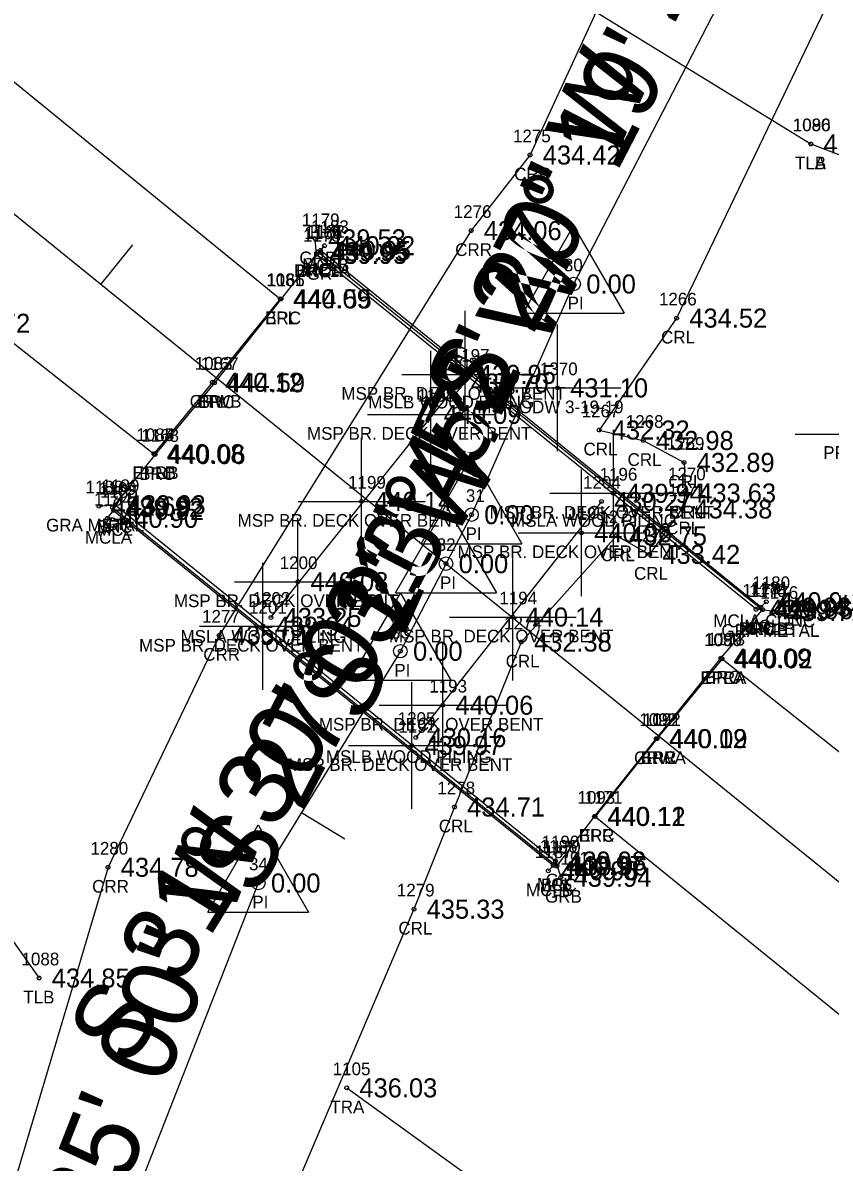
# Model space of a CAD drawing. Extents: x 1611865 to 1617004, y 775289 to 778546.
# Drawn here: x 1614429 to 1614492.7, y 777648.2 to 777738.1 of the extents above; entities that cross this region are included whole.
import ezdxf

# ---------------------------------------------------------------- set-up
doc = ezdxf.new("R2010")
doc.units = 0
for name, color, linetype in [('Default', 7, 'Continuous'), ('RD_EX_Bridge', 7, 'Continuous'), ('RD_EX_Bridge_txCode', 7, 'Continuous'), ('RD_EX_Conc', 7, 'Continuous'), ('RD_EX_Conc_txCode', 7, 'Continuous'), ('RD_EX_GuardRail', 7, 'Continuous'), ('RD_EX_GuardRail_txCode', 7, 'Continuous'), ('RD_EX_H2O', 7, 'Continuous'), ('RD_EX_H2O_txCode', 7, 'Continuous'), ('RD_EX_Misc', 7, 'Continuous'), ('RD_EX_Misc_txCode', 7, 'Continuous'), ('RD_EX_Road', 7, 'Continuous'), ('RD_EX_Road_txCode', 7, 'Continuous'), ('RD_EX_TX_Bridge_ELEV', 7, 'Continuous'), ('RD_EX_TX_Conc_ELEV', 7, 'Continuous'), ('RD_EX_TX_GuardRail_ELEV', 7, 'Continuous'), ('RD_EX_TX_H2O_ELEV', 7, 'Continuous'), ('RD_EX_TX_Misc_ELEV', 7, 'Continuous'), ('RD_EX_TX_Road_ELEV', 7, 'Continuous'), ('RD_EX_TX_VEG_ELEV', 7, 'Continuous'), ('RD_EX_UT', 7, 'Continuous'), ('RD_EX_UT_txCode', 7, 'Continuous'), ('RD_EX_VEG', 7, 'Continuous'), ('RD_EX_VEG_txCode', 7, 'Continuous'), ('RD_HC_Cl', 7, 'Continuous'), ('RD_HC_Data', 7, 'Continuous'), ('RD_HC_Data_Tic', 7, 'Continuous'), ('RD_HC_Survey_ELEV', 7, 'Continuous'), ('RD_HC_Survey_txCode', 7, 'Continuous'), ('RD_HC_txCode', 7, 'Continuous'), ('RD_SMD_Locator', 7, 'Continuous')]:
    doc.layers.add(name, color=color, linetype=linetype)

msp = doc.modelspace()

# ---------------------------------------------------------------- linework, layer by layer
at = {"layer": 'Default'}
for p, q in [((1614235.771, 777878.843), (1615250.563, 777057.494)), ((1614487.003, 777745.62), (1614472.452, 777717.464)), ((1614472.452, 777717.464), (1614464.407, 777699.284)), ((1614464.407, 777699.284), (1614458.798, 777688.523)), ((1614458.798, 777688.523), (1614447.603, 777670.255)), ((1614447.603, 777670.255), (1614430.278, 777626.087))]:
    msp.add_line(p, q, dxfattribs=at)
at = {"layer": 'RD_EX_Bridge'}
msp.add_line((1614452.321, 777720.005), (1614487.341, 777691.793), dxfattribs=at)
msp.add_lwpolyline([(1614452.321, 777720.005), (1614449.4, 777716.289), (1614444.153, 777709.679), (1614439.465, 777704.026), (1614436.12, 777699.854), (1614471.128, 777671.593), (1614474.101, 777675.503), (1614478.969, 777681.635), (1614484.046, 777687.977), (1614487.341, 777691.793)], dxfattribs=at)
at = {"layer": 'RD_EX_Conc'}
for points in [[(1614487.633, 777692.421), (1614487.198, 777691.999), (1614452.506, 777720.113), (1614452.825, 777720.485)], [(1614435.717, 777698.998), (1614436.195, 777699.618), (1614470.857, 777671.642), (1614470.453, 777671.217)]]:
    msp.add_lwpolyline(points, dxfattribs=at)
at = {"layer": 'RD_EX_GuardRail'}
for points in [[(1614488.257, 777691.653), (1614486.822, 777691.831), (1614452.199, 777719.801), (1614452.096, 777721.023)], [(1614435.05, 777699.96), (1614436.32, 777700.065), (1614471.025, 777671.987), (1614471.447, 777670.706)]]:
    msp.add_lwpolyline(points, dxfattribs=at)
at = {"layer": 'RD_EX_H2O'}
for p, q in [((1614471.182, 777704.278), (1614471.182, 777714.278)), ((1614466.182, 777709.278), (1614476.182, 777709.278))]:
    msp.add_line(p, q, dxfattribs=at)
for points in [[(1614634.128, 778230.422), (1614629.458, 778175.603), (1614612.201, 778126.551), (1614606.674, 778108.168), (1614610.575, 778089.24), (1614615.98, 778055.093), (1614603.68, 778033.92), (1614586.842, 777977.495), (1614567.105, 777927.459), (1614559.226, 777908.739), (1614527.556, 777868.787), (1614521.381, 777849.921), (1614507.997, 777820.034), (1614493.755, 777779.644), (1614479.272, 777749.866), (1614469.018, 777727.632), (1614464.372, 777721.672), (1614444.521, 777689.773), (1614435.763, 777671.493), (1614423.173, 777629.214)], [(1614612.84, 778001.087), (1614602.801, 777969.587), (1614583.96, 777919.694), (1614574.959, 777902.317), (1614550.816, 777861.375), (1614543.232, 777842.17), (1614528.681, 777813.751), (1614526.096, 777801.655), (1614517.134, 777789.525), (1614510.379, 777774.582), (1614495.519, 777745.969), (1614480.567, 777714.777), (1614474.457, 777705.957), (1614477.931, 777705.128), (1614481.152, 777703.399), (1614481.269, 777700.993), (1614480.974, 777699.735), (1614478.439, 777696.157), (1614475.819, 777697.62), (1614468.323, 777689.245), (1614463.059, 777676.245), (1614459.869, 777668.193), (1614440.888, 777623.611)]]:
    msp.add_lwpolyline(points, dxfattribs=at)
msp.add_circle((1614471.182, 777709.278), 0.15, dxfattribs=at)
at = {"layer": 'RD_EX_Misc'}
for p, q in [((1614463.914, 777705.341), (1614463.914, 777715.341)), ((1614461.204, 777702.188), (1614461.204, 777712.188)), ((1614458.914, 777710.341), (1614468.914, 777710.341)), ((1614448.599, 777691.185), (1614463.347, 777709.659)), ((1614456.204, 777707.188), (1614466.204, 777707.188)), ((1614455.741, 777695.333), (1614455.741, 777705.333)), ((1614475.582, 777695.97), (1614475.582, 777705.97)), ((1614473.068, 777692.857), (1614473.068, 777702.857)), ((1614470.582, 777700.97), (1614480.582, 777700.97)), ((1614450.741, 777700.333), (1614460.741, 777700.333)), ((1614474.646, 777700.329), (1614460.016, 777681.718)), ((1614450.717, 777688.998), (1614450.717, 777698.998)), ((1614468.068, 777697.857), (1614478.068, 777697.857)), ((1614447.974, 777685.491), (1614447.974, 777695.491)), ((1614467.664, 777686.215), (1614467.664, 777696.215)), ((1614445.717, 777693.998), (1614455.717, 777693.998)), ((1614462.664, 777691.215), (1614472.664, 777691.215)), ((1614442.974, 777690.491), (1614452.974, 777690.491)), ((1614462.14, 777679.268), (1614462.14, 777689.268)), ((1614459.7, 777676.092), (1614459.7, 777686.092)), ((1614457.14, 777684.268), (1614467.14, 777684.268)), ((1614454.7, 777681.092), (1614464.7, 777681.092))]:
    msp.add_line(p, q, dxfattribs=at)
at = {"layer": 'RD_EX_Road'}
for points in [[(1613868.873, 778104.152), (1613915.019, 778083.817), (1613960.162, 778062.2), (1614004.584, 778040.278), (1614048.838, 778015.985), (1614091.382, 777990.075), (1614134.355, 777962.6), (1614174.732, 777933.477), (1614192.07, 777920.583), (1614215.929, 777904.228), (1614254.595, 777873.045), (1614293.817, 777842.42), (1614371.745, 777779.588), (1614449.335, 777716.298), (1614443.983, 777709.717), (1614439.382, 777704.087)], [(1613862.136, 778087.922), (1613908.119, 778068.215), (1613952.955, 778047.38), (1613997.003, 778025.093), (1614041.162, 778001.628), (1614124.347, 777949.055), (1614164.513, 777920.905), (1614187.107, 777904.29), (1614205.267, 777889.822), (1614244.492, 777859.521), (1614283.421, 777829.445), (1614361.059, 777765.885), (1614439.382, 777704.087)], [(1614484.146, 777687.927), (1614479.014, 777681.629), (1614474.139, 777675.502), (1614516.402, 777641.229), (1614565.544, 777600.816), (1614593.956, 777577.927), (1614671.57, 777514.586), (1614748.82, 777451.937), (1614826.225, 777388.927), (1614903.915, 777325.971), (1614945.384, 777292.004), (1614981.733, 777262.806), (1615059.733, 777200.116)], [(1614484.146, 777687.927), (1614527.248, 777653.669), (1614604.966, 777591.413), (1614629.131, 777572.935), (1614683.141, 777529.853), (1614759.905, 777466.847), (1614838.214, 777403.779), (1614915.189, 777340.175), (1614934.979, 777324.495), (1615070.79, 777214.661)]]:
    msp.add_lwpolyline(points, dxfattribs=at)
at = {"layer": 'RD_EX_UT'}
msp.add_line((1614489.902, 777705.631), (1614493.371, 777705.631), dxfattribs=at)
at = {"layer": 'RD_EX_VEG'}
msp.add_line((1614401.116, 777703.978), (1614430.331, 777662.765), dxfattribs=at)
for points in [[(1613877.311, 778121.216), (1613921.053, 778100.025), (1613970.146, 778081.545), (1614014.029, 778056.89), (1614062.614, 778034.992), (1614105.061, 778008.153), (1614147.566, 777982.512), (1614187.981, 777952.836), (1614226.404, 777922.613), (1614267.617, 777889.852), (1614307.162, 777859.76), (1614385.115, 777793.649), (1614491.137, 777728.504)], [(1614491.137, 777728.504), (1614530.115, 777713.617), (1614552.514, 777682.013), (1614626.017, 777614.414), (1614703.99, 777552.849), (1614782.74, 777493.625), (1614860.243, 777426.798), (1615012.807, 777300.366), (1615089.651, 777237.197)], [(1614454.571, 777654.108), (1614501.278, 777620.357), (1614582.121, 777561.921), (1614657.514, 777498.9), (1614736.076, 777435.584), (1614812.67, 777372.039), (1614889.47, 777307.972), (1614967.463, 777245.162), (1615046.367, 777183.315)]]:
    msp.add_lwpolyline(points, dxfattribs=at)
at = {"layer": 'RD_HC_Cl'}
for p, q in [((1614235.771, 777878.843), (1615250.563, 777057.494)), ((1614487.003, 777745.62), (1614472.452, 777717.464)), ((1614472.452, 777717.464), (1614464.407, 777699.284)), ((1614464.407, 777699.284), (1614458.798, 777688.523)), ((1614458.798, 777688.523), (1614447.603, 777670.255)), ((1614447.603, 777670.255), (1614430.278, 777626.087))]:
    msp.add_line(p, q, dxfattribs=at)
at = {"layer": 'RD_HC_Data'}
for p, q in [((1614468.481, 777715.171), (1614472.453, 777722.051)), ((1614472.453, 777722.051), (1614476.422, 777715.171)), ((1614468.481, 777715.171), (1614476.422, 777715.171)), ((1614460.436, 777696.991), (1614464.408, 777703.871)), ((1614464.408, 777703.871), (1614468.376, 777696.991)), ((1614458.422, 777693.128), (1614462.394, 777700.007)), ((1614462.394, 777700.007), (1614466.363, 777693.128)), ((1614460.436, 777696.991), (1614468.376, 777696.991)), ((1614454.827, 777686.23), (1614458.799, 777693.11)), ((1614458.422, 777693.128), (1614466.363, 777693.128)), ((1614458.799, 777693.11), (1614462.767, 777686.23)), ((1614454.827, 777686.23), (1614462.767, 777686.23)), ((1614443.632, 777667.962), (1614447.604, 777674.842)), ((1614447.604, 777674.842), (1614451.572, 777667.962)), ((1614443.632, 777667.962), (1614451.572, 777667.962))]:
    msp.add_line(p, q, dxfattribs=at)
for centre in [(1614472.452, 777717.464), (1614464.407, 777699.284), (1614462.393, 777695.42), (1614458.798, 777688.523), (1614447.603, 777670.255)]:
    msp.add_circle(centre, 0.529, dxfattribs=at)
at = {"layer": 'RD_HC_Data_Tic'}
for p, q in [((1614435.19, 777717.437), (1614437.707, 777720.547)), ((1614451.014, 777675.822), (1614454.425, 777673.732))]:
    msp.add_line(p, q, dxfattribs=at)
at = {"layer": 'RD_SMD_Locator'}
for centre in [(1614491.137, 777728.504), (1614491.137, 777728.504), (1614469.018, 777727.632), (1614464.372, 777721.672), (1614452.096, 777721.023), (1614452.825, 777720.485), (1614452.199, 777719.801), (1614452.321, 777720.005), (1614452.321, 777720.005), (1614452.506, 777720.113), (1614472.452, 777717.464), (1614449.335, 777716.298), (1614449.4, 777716.289), (1614480.567, 777714.777), (1614443.983, 777709.717), (1614443.983, 777709.717), (1614444.153, 777709.679), (1614463.347, 777709.659), (1614463.914, 777710.341), (1614461.204, 777707.188), (1614474.457, 777705.957), (1614477.931, 777705.128), (1614439.382, 777704.087), (1614439.382, 777704.087), (1614439.465, 777704.026), (1614481.152, 777703.399), (1614475.582, 777700.97), (1614481.269, 777700.993), (1614435.05, 777699.96), (1614436.12, 777699.854), (1614436.32, 777700.065), (1614455.741, 777700.333), (1614474.646, 777700.329), (1614480.974, 777699.735), (1614435.717, 777698.998), (1614436.195, 777699.618), (1614464.407, 777699.284), (1614473.068, 777697.857), (1614475.819, 777697.62), (1614478.439, 777696.157), (1614462.393, 777695.42), (1614450.717, 777693.998), (1614486.822, 777691.831), (1614487.198, 777691.999), (1614487.341, 777691.793), (1614487.341, 777691.793), (1614487.633, 777692.421), (1614488.257, 777691.653), (1614448.599, 777691.185), (1614467.664, 777691.215), (1614447.974, 777690.491), (1614444.521, 777689.773), (1614468.323, 777689.245), (1614458.798, 777688.523), (1614484.046, 777687.977), (1614484.146, 777687.927), (1614484.146, 777687.927), (1614462.14, 777684.268), (1614459.7, 777681.092), (1614460.016, 777681.718), (1614478.969, 777681.635), (1614479.014, 777681.629), (1614479.014, 777681.629), (1614463.059, 777676.245), (1614474.101, 777675.503), (1614474.139, 777675.502), (1614471.025, 777671.987), (1614435.763, 777671.493), (1614470.453, 777671.217), (1614470.857, 777671.642), (1614471.128, 777671.593), (1614447.603, 777670.255), (1614471.447, 777670.706), (1614459.869, 777668.193), (1614430.331, 777662.765), (1614454.571, 777654.108)]:
    msp.add_circle(centre, 0.15, dxfattribs=at)

# ---------------------------------------------------------------- texts
at = {"layer": 'RD_EX_Bridge_txCode'}
for s, p in [('1164', (1614451.235, 777721.005)), ('1165', (1614451.235, 777721.005)), ('BRC1A', (1614450.416, 777718.005)), ('BRCA', (1614450.581, 777718.005)), ('1166', (1614448.289, 777717.289)), ('BRC', (1614448.148, 777714.289)), ('1167', (1614443.067, 777710.679)), ('BRC', (1614442.901, 777707.679)), ('1168', (1614438.378, 777705.026)), ('BRC', (1614438.213, 777702.026)), ('1169', (1614435.033, 777700.854)), ('BRC', (1614434.868, 777697.854)), ('1174', (1614486.278, 777692.793)), ('1175', (1614486.278, 777692.793)), ('1173', (1614482.983, 777688.977)), ('BRC1B', (1614485.451, 777689.793)), ('BRCB', (1614485.617, 777689.793)), ('BRC', (1614482.794, 777685.977)), ('1172', (1614477.906, 777682.635)), ('BRC', (1614477.717, 777679.635)), ('1171', (1614473.321, 777676.503)), ('BRC', (1614472.849, 777673.503)), ('1170', (1614470.026, 777672.593)), ('BRC', (1614469.876, 777669.593))]:
    msp.add_text(s, height=1, dxfattribs=at).set_placement(p)
at = {"layer": 'RD_EX_Conc_txCode'}
for s, p in [('1183', (1614451.762, 777721.485)), ('1182', (1614451.443, 777721.113)), ('MCLB', (1614451.061, 777718.485)), ('MCL', (1614451.215, 777718.113)), ('1184', (1614434.654, 777699.998)), ('1185', (1614435.132, 777700.618)), ('MCL', (1614434.904, 777697.618)), ('MCLA', (1614433.937, 777696.998)), ('1181', (1614486.419, 777692.999)), ('1180', (1614486.531, 777693.421)), ('MCLA CONC', (1614483.46, 777690.421)), ('MCL', (1614485.907, 777689.999)), ('1187', (1614469.39, 777672.217)), ('1186', (1614469.77, 777672.642)), ('MCLB', (1614468.689, 777669.217)), ('MCL', (1614469.565, 777669.642))]:
    msp.add_text(s, height=1, dxfattribs=at).set_placement(p)
at = {"layer": 'RD_EX_GuardRail_txCode'}
for s, p in [('1179', (1614451.033, 777722.023)), ('1178', (1614451.136, 777720.801)), ('GRB', (1614450.844, 777719.023)), ('GR', (1614451.42, 777717.801)), ('1188', (1614433.987, 777700.96)), ('1189', (1614435.257, 777701.065)), ('GRA METAL', (1614430.885, 777697.96)), ('GR', (1614435.54, 777698.065)), ('1177', (1614485.759, 777692.831)), ('1176', (1614487.17, 777692.653)), ('GRA METAL', (1614484.092, 777689.653)), ('GR', (1614486.042, 777689.831)), ('1190', (1614469.923, 777672.987)), ('1191', (1614470.667, 777671.706)), ('GR', (1614470.246, 777669.987)), ('GRB', (1614470.195, 777668.706))]:
    msp.add_text(s, height=1, dxfattribs=at).set_placement(p)
at = {"layer": 'RD_EX_H2O_txCode'}
for s, p in [('1275', (1614467.672, 777728.632)), ('CRR', (1614467.766, 777725.632)), ('1276', (1614463.002, 777722.672)), ('CRR', (1614463.12, 777719.672)), ('1266', (1614479.173, 777715.777)), ('CRL', (1614479.339, 777712.777)), ('1370', (1614469.796, 777710.278)), ('MSP ODW 3-19-19', (1614464.867, 777707.278)), ('1267', (1614473.087, 777706.957)), ('1268', (1614476.561, 777706.128)), ('1269', (1614479.782, 777704.399)), ('CRL', (1614473.229, 777703.957)), ('CRL', (1614476.703, 777703.128)), ('1270', (1614479.883, 777701.993)), ('CRL', (1614479.924, 777701.399)), ('1271', (1614479.911, 777700.735)), ('CRL', (1614480.041, 777698.993)), ('1273', (1614474.473, 777698.62)), ('1272', (1614477.093, 777697.157)), ('CRL', (1614479.746, 777697.735)), ('CRL', (1614474.591, 777695.62)), ('CRL', (1614477.211, 777694.157)), ('1277', (1614443.174, 777690.773)), ('1274', (1614466.977, 777690.245)), ('CRR', (1614443.269, 777687.773)), ('CRL', (1614467.095, 777687.245)), ('1278', (1614461.712, 777677.245)), ('CRL', (1614461.83, 777674.245)), ('1280', (1614434.377, 777672.493)), ('CRR', (1614434.511, 777669.493)), ('1279', (1614458.522, 777669.193)), ('CRL', (1614458.64, 777666.193))]:
    msp.add_text(s, height=1, dxfattribs=at).set_placement(p)
at = {"layer": 'RD_EX_Misc_txCode'}
for s, p in [('1203', (1614461.931, 777710.659)), ('1197', (1614462.851, 777711.341)), ('MSP BR. DECK OVER BENT', (1614454.15, 777708.341)), ('1198', (1614460.141, 777708.188)), ('MSLB WOOD PILING', (1614456.263, 777707.659)), ('MSP BR. DECK OVER BENT', (1614451.44, 777705.188)), ('1196', (1614474.496, 777701.97)), ('1199', (1614454.678, 777701.333)), ('1204', (1614473.194, 777701.329)), ('MSP BR. DECK OVER BENT', (1614465.819, 777698.97)), ('1195', (1614472.005, 777698.857)), ('MSP BR. DECK OVER BENT', (1614445.977, 777698.333)), ('MSLA WOOD PILING', (1614467.521, 777698.329)), ('MSP BR. DECK OVER BENT', (1614463.304, 777695.857)), ('1200', (1614449.292, 777694.998)), ('MSP BR. DECK OVER BENT', (1614440.953, 777691.998)), ('1202', (1614447.153, 777692.185)), ('1194', (1614466.601, 777692.215)), ('1201', (1614446.872, 777691.491)), ('MSLA WOOD PILING', (1614441.474, 777689.185)), ('MSP BR. DECK OVER BENT', (1614457.901, 777689.215)), ('MSP BR. DECK OVER BENT', (1614438.21, 777688.491)), ('1193', (1614461.077, 777685.268)), ('1205', (1614458.587, 777682.718)), ('MSP BR. DECK OVER BENT', (1614452.376, 777682.268)), ('1192', (1614458.637, 777682.092)), ('MSP BR. DECK OVER BENT', (1614449.936, 777679.092)), ('MSLB WOOD PILING', (1614452.932, 777679.718))]:
    msp.add_text(s, height=1, dxfattribs=at).set_placement(p)
at = {"layer": 'RD_EX_Road_txCode'}
for s, p in [('1081', (1614448.232, 777717.298)), ('EPL', (1614448.13, 777714.298)), ('1083', (1614442.597, 777710.717)), ('EPL', (1614442.778, 777707.717)), ('1084', (1614437.996, 777705.087)), ('1085', (1614437.996, 777705.087)), ('EPRB', (1614437.682, 777702.087)), ('EPLB', (1614437.705, 777702.087)), ('1090', (1614482.721, 777688.927)), ('1089', (1614482.76, 777688.927)), ('EPRA', (1614482.429, 777685.927)), ('EPLA', (1614482.453, 777685.927)), ('1091', (1614477.912, 777682.629)), ('EPR', (1614477.786, 777679.629)), ('1093', (1614472.753, 777676.502)), ('EPR', (1614472.911, 777673.502))]:
    msp.add_text(s, height=1, dxfattribs=at).set_placement(p)
at = {"layer": 'RD_EX_TX_Bridge_ELEV'}
for s, p in [('439.95', (1614453.321, 777719.255)), ('439.95', (1614453.321, 777719.255)), ('444.55', (1614450.4, 777715.539)), ('444.59', (1614445.153, 777708.929)), ('440.06', (1614440.465, 777703.276)), ('439.92', (1614437.12, 777699.104)), ('439.96', (1614488.341, 777691.043)), ('439.96', (1614488.341, 777691.043)), ('440.09', (1614485.046, 777687.227)), ('440.12', (1614479.969, 777680.885)), ('440.11', (1614475.101, 777674.753)), ('439.96', (1614472.128, 777670.843))]:
    msp.add_text(s, height=1.5, dxfattribs=at).set_placement(p)
at = {"layer": 'RD_EX_TX_Conc_ELEV'}
for s, p in [('440.95', (1614453.506, 777719.363)), ('440.92', (1614453.825, 777719.735)), ('440.92', (1614437.195, 777698.868)), ('440.90', (1614436.717, 777698.248)), ('440.93', (1614488.198, 777691.249)), ('440.90', (1614488.633, 777691.671)), ('440.97', (1614471.857, 777670.892)), ('440.96', (1614471.453, 777670.467))]:
    msp.add_text(s, height=1.5, dxfattribs=at).set_placement(p)
at = {"layer": 'RD_EX_TX_GuardRail_ELEV'}
for s, p in [('439.53', (1614453.096, 777720.273)), ('439.95', (1614453.199, 777719.051)), ('439.93', (1614437.32, 777699.315)), ('439.69', (1614436.05, 777699.21)), ('439.94', (1614487.822, 777691.081)), ('439.71', (1614489.257, 777690.903)), ('439.98', (1614472.025, 777671.237)), ('439.94', (1614472.447, 777669.956))]:
    msp.add_text(s, height=1.5, dxfattribs=at).set_placement(p)
at = {"layer": 'RD_EX_TX_H2O_ELEV'}
for s, p in [('434.42', (1614470.018, 777726.882)), ('434.06', (1614465.372, 777720.922)), ('434.52', (1614481.567, 777714.027)), ('432.32', (1614475.457, 777705.207)), ('432.98', (1614478.931, 777704.378)), ('432.89', (1614482.152, 777702.649)), ('433.63', (1614482.269, 777700.243)), ('434.38', (1614481.974, 777698.985)), ('432.75', (1614476.819, 777696.87)), ('433.42', (1614479.439, 777695.407)), ('435.01', (1614445.521, 777689.023)), ('432.38', (1614469.323, 777688.495)), ('434.71', (1614464.059, 777675.495)), ('434.78', (1614436.763, 777670.743)), ('435.33', (1614460.869, 777667.443))]:
    msp.add_text(s, height=1.5, dxfattribs=at).set_placement(p)
at = {"layer": 'RD_EX_TX_Misc_ELEV'}
for s, p in [('439.95', (1614464.914, 777709.591)), ('430.70', (1614464.347, 777708.909)), ('431.10', (1614472.182, 777708.528)), ('440.09', (1614462.204, 777706.438)), ('439.94', (1614476.582, 777700.22)), ('440.14', (1614456.741, 777699.583)), ('430.27', (1614475.646, 777699.579)), ('440.06', (1614474.068, 777697.107)), ('440.08', (1614451.717, 777693.248)), ('433.25', (1614449.599, 777690.435)), ('440.14', (1614468.664, 777690.465)), ('439.94', (1614448.974, 777689.741)), ('440.06', (1614463.14, 777683.518)), ('430.16', (1614461.016, 777680.968)), ('439.97', (1614460.7, 777680.342))]:
    msp.add_text(s, height=1.5, dxfattribs=at).set_placement(p)
at = {"layer": 'RD_EX_TX_Road_ELEV'}
for s, p in [('440.09', (1614450.335, 777715.548)), ('440.12', (1614444.983, 777708.967)), ('440.08', (1614440.382, 777703.337)), ('440.08', (1614440.382, 777703.337)), ('440.02', (1614485.146, 777687.177)), ('440.02', (1614485.146, 777687.177)), ('440.09', (1614480.014, 777680.879)), ('440.12', (1614475.139, 777674.752))]:
    msp.add_text(s, height=1.5, dxfattribs=at).set_placement(p)
at = {"layer": 'RD_EX_TX_VEG_ELEV'}
for s, p in [('434.81', (1614492.137, 777727.754)), ('434.81', (1614492.137, 777727.754)), ('434.85', (1614431.331, 777662.015)), ('436.03', (1614455.571, 777653.358))]:
    msp.add_text(s, height=1.5, dxfattribs=at).set_placement(p)
at = {"layer": 'RD_EX_UT_txCode'}
msp.add_text('PP 046491', height=1, dxfattribs=at).set_placement((1614492.117, 777703.684))
at = {"layer": 'RD_EX_VEG_txCode'}
for s, p in [('1080', (1614489.712, 777729.504)), ('1096', (1614489.728, 777729.504)), ('TLA', (1614489.878, 777726.504)), ('TLB', (1614489.893, 777726.504)), ('1088', (1614428.945, 777663.765)), ('TLB', (1614429.087, 777660.765)), ('1105', (1614453.468, 777655.108)), ('TRA', (1614453.287, 777652.108))]:
    msp.add_text(s, height=1, dxfattribs=at).set_placement(p)
at = {"layer": 'RD_HC_Data'}
for s, rotation, p in [('S 27%%d 19\' 44" W', 62.67125, (1614465.716, 777706.606)), ('S 23%%d 52\' 20" W', 66.12773, (1614455.946, 777682.639)), ('S 27%%d 31\' 47" W', 62.47016, (1614447.503, 777669.017)), ('S 31%%d 30\' 01" W', 58.49961, (1614437.411, 777655.538)), ('S 21%%d 25\' 00" W', 68.5833, (1614427.571, 777621.924))]:
    msp.add_text(s, height=6, rotation=rotation, dxfattribs=at).set_placement(p)
at = {"layer": 'RD_HC_Survey_ELEV'}
for s, p in [('0.00', (1614473.452, 777716.714)), ('439.72', (1614423.495, 777713.621)), ('440.12', (1614444.983, 777708.967)), ('0.00', (1614465.407, 777698.534)), ('0.00', (1614463.393, 777694.67)), ('0.00', (1614459.798, 777687.773)), ('440.09', (1614480.014, 777680.879)), ('0.00', (1614448.603, 777669.505))]:
    msp.add_text(s, height=1.5, dxfattribs=at).set_placement(p)
at = {"layer": 'RD_HC_Survey_txCode'}
for s, p in [('1082', (1614442.597, 777710.717)), ('CRWB', (1614442.196, 777707.717)), ('1092', (1614477.628, 777682.629)), ('CRWA', (1614477.211, 777679.629))]:
    msp.add_text(s, height=1, dxfattribs=at).set_placement(p)
at = {"layer": 'RD_HC_txCode'}
for s, p in [('30', (1614471.681, 777718.464)), ('PI', (1614471.98, 777715.464)), ('31', (1614463.958, 777700.284)), ('PI', (1614463.934, 777697.284)), ('32', (1614461.66, 777696.42)), ('PI', (1614461.92, 777693.42)), ('33', (1614458.065, 777689.523)), ('PI', (1614458.325, 777686.523)), ('34', (1614446.87, 777671.255)), ('PI', (1614447.13, 777668.255))]:
    msp.add_text(s, height=1, dxfattribs=at).set_placement(p)

doc.saveas('drawing.dxf')
